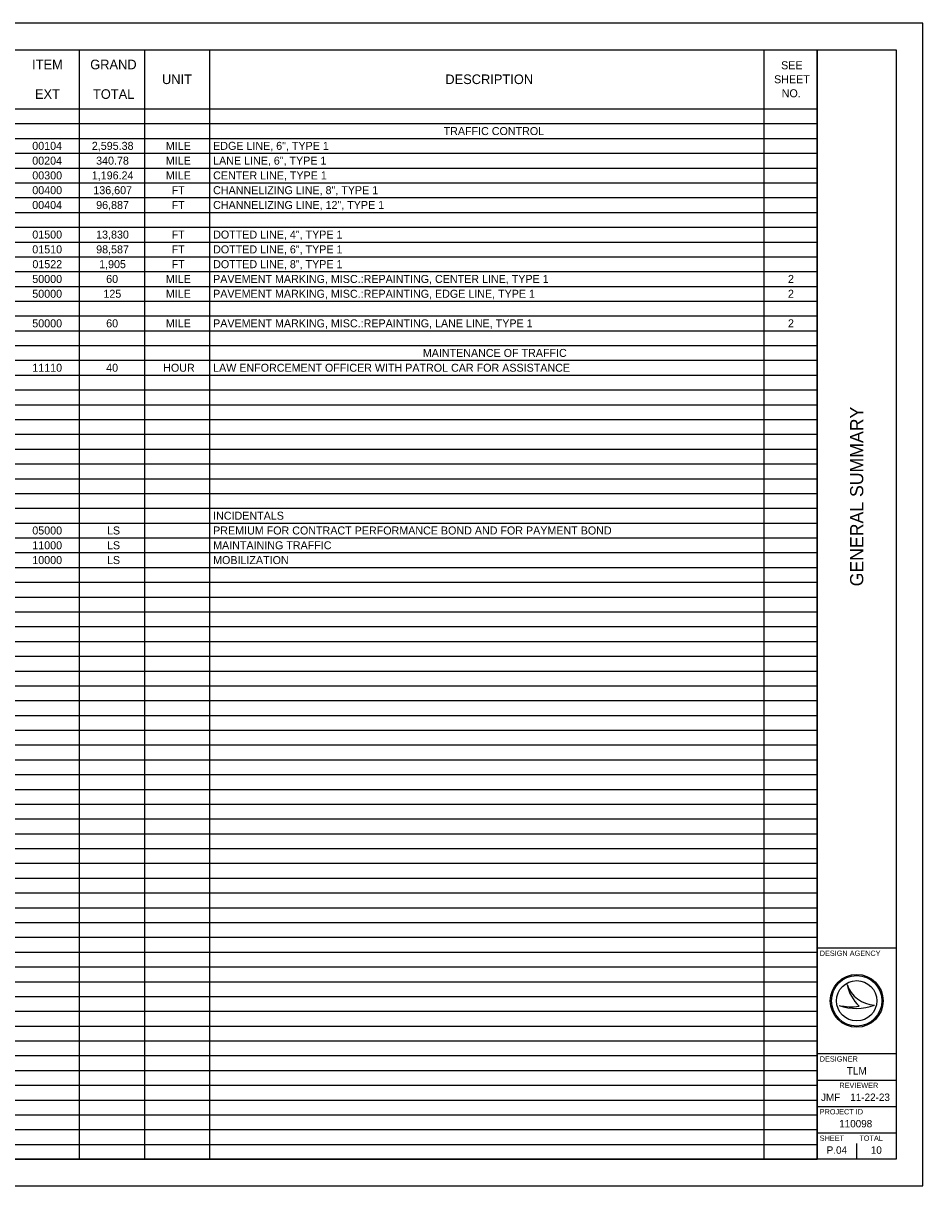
# Model space of a CAD drawing. Extents: x 0 to 34, y 0 to 22.
# Drawn here: x 16.98 to 34, y 0 to 22 of the extents above; entities that cross this region are included whole.
import ezdxf

# ---------------------------------------------------------------- set-up
doc = ezdxf.new("R2010")
doc.units = 0
for name, color, linetype in [('SH_Border', 7, 'Continuous'), ('SH_Cut_Line', 7, 'Continuous'), ('SH_Data', 7, 'Continuous'), ('SH_Text', 7, 'Continuous')]:
    doc.layers.add(name, color=color, linetype=linetype)

msp = doc.modelspace()

# ---------------------------------------------------------------- linework, layer by layer
at = {"layer": 'SH_Border'}
for p, q in [((32, 0.5), (32, 21.5)), ((32, 4.5), (33.5, 4.5)), ((32, 2.5), (33.5, 2.5)), ((32, 2), (33.5, 2)), ((32, 1.5), (33.5, 1.5)), ((32, 1), (33.5, 1))]:
    msp.add_line(p, q, dxfattribs=at)
msp.add_lwpolyline([(1.5, 21.5), (33.5, 21.5), (33.5, 0.5), (1.5, 0.5)], close=True, dxfattribs=at)
at = {"layer": 'SH_Cut_Line'}
msp.add_lwpolyline([(0, 0), (34, 0), (34, 22), (0, 22)], close=True, dxfattribs=at)
at = {"layer": 'SH_Data'}
for p, q in [((32.567, 3.81), (32.567, 3.81)), ((32.417, 3.41), (32.417, 3.41)), ((32.75, 3.5), (32.75, 3.5)), ((33.087, 3.419), (33.087, 3.419)), ((32.375, 0.675), (32.375, 0.675)), ((32.75, 0.5), (32.75, 0.8))]:
    msp.add_line(p, q, dxfattribs=at)
for radius in [0.5, 0.477, 0.477, 0.382]:
    msp.add_circle((32.75, 3.5), radius, dxfattribs=at)
for centre, radius, start, end in [((33.116, 3.998), 0.58, 198.9257, 198.9319), ((33.347, 3.97), 0.796, 191.6379, 191.6421), ((33.116, 3.998), 0.58, 198.9319, 267.1657), ((33.347, 3.97), 0.796, 191.6421, 226.0947), ((32.739, 4.37), 1.013, 251.4576, 290.0832), ((32.648, 4.654), 1.266, 259.4964, 259.4995), ((32.739, 4.37), 1.013, 251.4527, 251.4576), ((32.648, 4.654), 1.266, 259.4995, 276.6672)]:
    msp.add_arc(centre, radius, start, end, dxfattribs=at)
at = {"layer": 'SH_Text'}
for p, q in [((1.5, 21.5), (32, 21.5)), ((18.035, 21.5), (18.035, 0.502)), ((19.27, 21.5), (19.27, 0.502)), ((20.505, 21.5), (20.505, 0.502)), ((30.995, 21.5), (30.995, 0.502)), ((32, 21.5), (32, 0.502)), ((1.5, 20.38), (32, 20.38)), ((1.5, 20.1), (32, 20.1)), ((1.5, 19.82), (32, 19.82)), ((1.5, 19.54), (32, 19.54)), ((1.5, 19.26), (32, 19.26)), ((1.5, 18.98), (32, 18.98)), ((1.5, 18.7), (32, 18.7)), ((1.5, 18.42), (32, 18.42)), ((1.5, 18.14), (32, 18.14)), ((1.5, 17.86), (32, 17.86)), ((1.5, 17.58), (32, 17.58)), ((1.5, 17.3), (32, 17.3)), ((1.5, 17.021), (32, 17.021)), ((1.5, 16.741), (32, 16.741)), ((1.5, 16.461), (32, 16.461)), ((1.5, 16.181), (32, 16.181)), ((1.5, 15.901), (32, 15.901)), ((1.5, 15.621), (32, 15.621)), ((1.5, 15.341), (32, 15.341)), ((1.5, 15.061), (32, 15.061)), ((1.5, 14.781), (32, 14.781)), ((1.5, 14.501), (32, 14.501)), ((1.5, 14.221), (32, 14.221)), ((1.5, 13.941), (32, 13.941)), ((1.5, 13.661), (32, 13.661)), ((1.5, 13.381), (32, 13.381)), ((1.5, 13.101), (32, 13.101)), ((1.5, 12.821), (32, 12.821)), ((1.5, 12.541), (32, 12.541)), ((1.5, 12.261), (32, 12.261)), ((1.5, 11.981), (32, 11.981)), ((1.5, 11.701), (32, 11.701)), ((1.5, 11.421), (32, 11.421)), ((1.5, 11.141), (32, 11.141)), ((1.5, 10.861), (32, 10.861)), ((1.5, 10.581), (32, 10.581)), ((1.5, 10.301), (32, 10.301)), ((1.5, 10.021), (32, 10.021)), ((1.5, 9.741), (32, 9.741)), ((1.5, 9.461), (32, 9.461)), ((1.5, 9.181), (32, 9.181)), ((1.5, 8.901), (32, 8.901)), ((1.5, 8.621), (32, 8.621)), ((1.5, 8.342), (32, 8.342)), ((1.5, 8.062), (32, 8.062)), ((1.5, 7.782), (32, 7.782)), ((1.5, 7.502), (32, 7.502)), ((1.5, 7.222), (32, 7.222)), ((1.5, 6.942), (32, 6.942)), ((1.5, 6.662), (32, 6.662)), ((1.5, 6.382), (32, 6.382)), ((1.5, 6.102), (32, 6.102)), ((1.5, 5.822), (32, 5.822)), ((1.5, 5.542), (32, 5.542)), ((1.5, 5.262), (32, 5.262)), ((1.5, 4.982), (32, 4.982)), ((1.5, 4.702), (32, 4.702)), ((1.5, 4.422), (32, 4.422)), ((1.5, 4.142), (32, 4.142)), ((1.5, 3.862), (32, 3.862)), ((1.5, 3.582), (32, 3.582)), ((1.5, 3.302), (32, 3.302)), ((1.5, 3.022), (32, 3.022)), ((1.5, 2.742), (32, 2.742)), ((1.5, 2.462), (32, 2.462)), ((1.5, 2.182), (32, 2.182)), ((1.5, 1.902), (32, 1.902)), ((1.5, 1.622), (32, 1.622)), ((1.5, 1.342), (32, 1.342)), ((1.5, 1.062), (32, 1.062)), ((1.5, 0.782), (32, 0.782)), ((1.5, 0.502), (32, 0.502))]:
    msp.add_line(p, q, dxfattribs=at)

# ---------------------------------------------------------------- texts
at = {"layer": 'SH_Data'}
msp.add_text('GENERAL SUMMARY', height=0.25, rotation=90, dxfattribs=at).set_placement((32.875, 11.344))
for s, height, p in [('DESIGN AGENCY', 0.1, (32.05, 4.35)), ('DESIGNER', 0.1, (32.05, 2.35)), ('TLM', 0.14, (32.565, 2.105)), ('REVIEWER', 0.1, (32.422, 1.85)), ('JMF', 0.14, (32.075, 1.605)), ('11-22-23', 0.14, (32.629, 1.605)), ('PROJECT ID', 0.1, (32.05, 1.35)), ('110098', 0.14, (32.419, 1.105)), ('SHEET', 0.1, (32.05, 0.85)), ('TOTAL', 0.1, (32.8, 0.85)), ('P.04', 0.14, (32.182, 0.605)), ('10', 0.14, (33.017, 0.605))]:
    msp.add_text(s, height=height, dxfattribs=at).set_placement(p)
at = {"layer": 'SH_Text'}
for s, height, p in [('ITEM', 0.1818, (17.145, 21.129)), ('GRAND', 0.1818, (18.245, 21.129)), ('SEE ', 0.1515, (31.32, 21.129)), ('UNIT', 0.1818, (19.604, 20.849)), ('DESCRIPTION', 0.18181, (24.965, 20.849)), ('SHEET ', 0.1515, (31.187, 20.864)), ('EXT', 0.1818, (17.199, 20.569)), ('TOTAL', 0.1818, (18.297, 20.569)), ('NO.', 0.1515, (31.331, 20.599)), ('TRAFFIC CONTROL', 0.15151, (24.933, 19.884)), ('00104', 0.1515, (17.148, 19.604)), ('2,595.38', 0.1515, (18.276, 19.604)), ('MILE', 0.1515, (19.676, 19.604)), ('EDGE LINE, 6", TYPE 1', 0.15151, (20.571, 19.604)), ('00204', 0.1515, (17.148, 19.324)), ('340.78', 0.1515, (18.357, 19.324)), ('MILE', 0.1515, (19.676, 19.324)), ('LANE LINE, 6", TYPE 1', 0.15151, (20.571, 19.324)), ('00300', 0.1515, (17.149, 19.045)), ('1,196.24', 0.1515, (18.275, 19.045)), ('MILE', 0.1515, (19.676, 19.045)), ('CENTER LINE, TYPE 1', 0.15151, (20.571, 19.045)), ('00400', 0.1515, (17.149, 18.765)), ('136,607', 0.1515, (18.304, 18.765)), ('FT', 0.1515, (19.786, 18.765)), ('CHANNELIZING LINE, 8", TYPE 1', 0.15151, (20.571, 18.765)), ('00404', 0.1515, (17.148, 18.485)), ('96,887', 0.1515, (18.358, 18.485)), ('FT', 0.1515, (19.786, 18.485)), ('CHANNELIZING LINE, 12", TYPE 1', 0.15151, (20.571, 18.485)), ('01500', 0.1515, (17.149, 17.925)), ('13,830', 0.1515, (18.357, 17.925)), ('FT', 0.1515, (19.786, 17.925)), ('DOTTED LINE, 4", TYPE 1', 0.15151, (20.571, 17.925)), ('01510', 0.1515, (17.149, 17.645)), ('98,587', 0.1515, (18.358, 17.645)), ('FT', 0.1515, (19.786, 17.645)), ('DOTTED LINE, 6", TYPE 1', 0.15151, (20.571, 17.645)), ('01522', 0.1515, (17.151, 17.365)), ('1,905', 0.1515, (18.414, 17.365)), ('FT', 0.1515, (19.786, 17.365)), ('DOTTED LINE, 8", TYPE 1', 0.15151, (20.571, 17.365)), ('50000', 0.1515, (17.149, 17.085)), ('60', 0.1515, (18.547, 17.085)), ('MILE', 0.1515, (19.676, 17.085)), ('PAVEMENT MARKING, MISC.:REPAINTING, CENTER LINE, TYPE 1', 0.15151, (20.571, 17.085)), ('2', 0.152, (31.449, 17.085)), ('50000', 0.1515, (17.149, 16.805)), ('125', 0.1515, (18.495, 16.805)), ('MILE', 0.1515, (19.676, 16.805)), ('PAVEMENT MARKING, MISC.:REPAINTING, EDGE LINE, TYPE 1', 0.15151, (20.571, 16.805)), ('2', 0.152, (31.449, 16.805)), ('50000', 0.1515, (17.149, 16.245)), ('60', 0.1515, (18.547, 16.245)), ('MILE', 0.1515, (19.676, 16.245)), ('PAVEMENT MARKING, MISC.:REPAINTING, LANE LINE, TYPE 1', 0.15151, (20.571, 16.245)), ('2', 0.152, (31.449, 16.245)), ('MAINTENANCE OF TRAFFIC', 0.15151, (24.539, 15.685)), ('11110', 0.1515, (17.149, 15.405)), ('40', 0.1515, (18.547, 15.405)), ('HOUR', 0.1515, (19.626, 15.405)), ('LAW ENFORCEMENT OFFICER WITH PATROL CAR FOR ASSISTANCE', 0.15151, (20.571, 15.405)), ('INCIDENTALS', 0.15151, (20.571, 12.605)), ('05000', 0.1515, (17.149, 12.325)), ('LS', 0.1515, (18.562, 12.325)), ('PREMIUM FOR CONTRACT PERFORMANCE BOND AND FOR PAYMENT BOND', 0.15151, (20.571, 12.325)), ('11000', 0.1515, (17.149, 12.045)), ('LS', 0.1515, (18.562, 12.045)), ('MAINTAINING TRAFFIC', 0.15151, (20.571, 12.045)), ('10000', 0.1515, (17.149, 11.765)), ('LS', 0.1515, (18.562, 11.765)), ('MOBILIZATION', 0.15151, (20.571, 11.765))]:
    msp.add_text(s, height=height, dxfattribs=at).set_placement(p)

doc.saveas('drawing.dxf')
